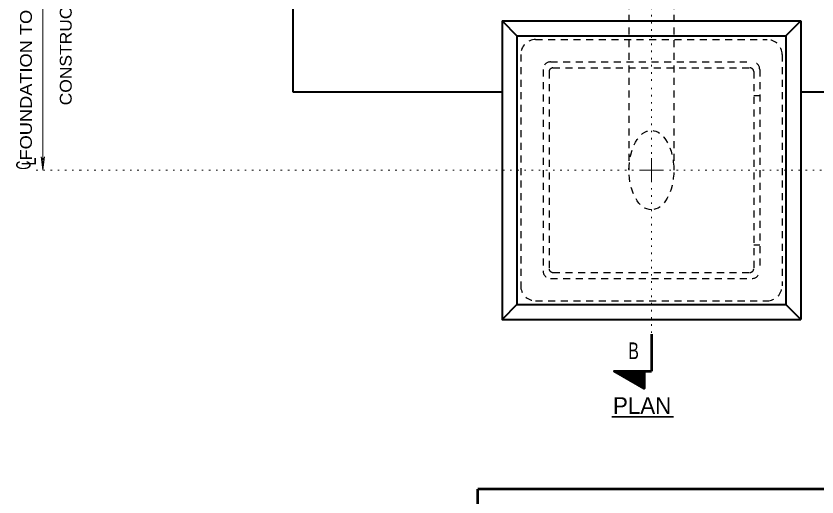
# Model space of a CAD drawing. Extents: x 312583 to 312854, y 144419 to 144597.
# Drawn here: x 312766.7 to 312818.1, y 144512 to 144542.9 of the extents above; entities that cross this region are included whole.
import ezdxf
from ezdxf.enums import TextEntityAlignment as Align

# ---------------------------------------------------------------- set-up
doc = ezdxf.new("R2010")
doc.units = 0
doc.header["$LTSCALE"] = 0.3
doc.linetypes.add('DOTTED', pattern=[1.5, 0.3, -1.2])
doc.linetypes.add('SHORT_DASHED', pattern=[2.7, 1.5, -1.2])
doc.layers.add('1', color=7, linetype='Continuous', lineweight=13)

msp = doc.modelspace()

# ---------------------------------------------------------------- linework, layer by layer
at = {"layer": '1'}
for p, q in [((312768.4232, 144532.9662), (312768.4232, 144573.9982)), ((312768.3158, 144533.8326), (312768.4232, 144533.5566)), ((312768.4232, 144532.9662), (312768.3158, 144533.8326)), ((312768.5305, 144533.8326), (312768.4232, 144533.5566)), ((312768.4232, 144532.9662), (312768.5305, 144533.8326)), ((312807.4758, 144532.9662), (312807.4758, 144533.7329)), ((312807.4758, 144532.9662), (312806.7092, 144532.9662)), ((312807.4758, 144532.9662), (312808.2425, 144532.9662)), ((312807.4758, 144532.9662), (312807.4758, 144532.1996))]:
    msp.add_line(p, q, dxfattribs=at)
at = {"layer": '1', "lineweight": 40}
for p, q in [((312784.4758, 144566.7456), (312784.4758, 144537.9956)), ((312797.8925, 144542.5496), (312817.0592, 144542.5496)), ((312797.8925, 144542.5496), (312798.8508, 144541.5912)), ((312816.1008, 144541.5912), (312817.0592, 144542.5496)), ((312817.0592, 144542.5496), (312817.0592, 144523.3829)), ((312798.8508, 144541.5912), (312798.8508, 144524.3412)), ((312798.8508, 144541.5912), (312816.1008, 144541.5912)), ((312816.1008, 144541.5912), (312816.1008, 144524.3412)), ((312784.4758, 144537.9956), (312797.8925, 144537.9956)), ((312817.0592, 144537.9956), (312830.4758, 144537.9956)), ((312798.8508, 144524.3412), (312797.8925, 144523.3829)), ((312798.8508, 144524.3412), (312816.1008, 144524.3412)), ((312816.1008, 144524.3412), (312817.0592, 144523.3829))]:
    msp.add_line(p, q, dxfattribs=at)
at = {"layer": '1', "linetype": 'DOTTED'}
for p, q in [((312807.4758, 144551.2206), (312807.4758, 144538.5706)), ((312807.4758, 144534.0166), (312807.4758, 144538.5706)), ((312807.4758, 144531.8162), (312807.4758, 144522.4476))]:
    msp.add_line(p, q, dxfattribs=at)
at = {"layer": '1', "linetype": 'SHORT_DASHED', "lineweight": 25}
for p, q in [((312806.0345, 144543.7456), (312806.0345, 144532.9662)), ((312808.9095, 144543.7456), (312808.9095, 144532.9662)), ((312800.0468, 144541.3536), (312814.8972, 144541.3536)), ((312799.0885, 144540.3952), (312799.0885, 144525.5372)), ((312815.8555, 144540.3952), (312815.8555, 144525.5372)), ((312801.0052, 144539.9122), (312813.9388, 144539.9122)), ((312800.5222, 144539.4369), (312800.5222, 144526.4956)), ((312800.9055, 144539.2912), (312800.9055, 144526.6412)), ((312801.1508, 144539.5289), (312813.8008, 144539.5289)), ((312814.0385, 144539.2912), (312814.0385, 144526.6412)), ((312814.4218, 144539.4369), (312814.4218, 144526.4956)), ((312814.0385, 144537.7579), (312814.4218, 144537.7579)), ((312814.0385, 144528.1746), (312814.4218, 144528.1746)), ((312801.1508, 144526.4036), (312813.8008, 144526.4036)), ((312801.0052, 144526.0202), (312813.9388, 144526.0202)), ((312800.0468, 144524.5789), (312814.8972, 144524.5789))]:
    msp.add_line(p, q, dxfattribs=at)
at = {"layer": '1', "lineweight": 53}
for p, q in [((312807.4758, 144522.4476), (312807.4758, 144520.0556)), ((312807.0005, 144520.0556), (312807.4758, 144520.0556)), ((312796.3473, 144432.4767), (312796.3473, 144512.4926)), ((312849, 144512.4926), (312796.3473, 144512.4926))]:
    msp.add_line(p, q, dxfattribs=at)
at = {"layer": '1', "lineweight": 35}
for p, q in [((312805.0992, 144520.0556), (312805.0992, 144520.0402)), ((312805.1298, 144520.0556), (312805.1222, 144520.0326)), ((312805.1605, 144520.0556), (312805.1375, 144520.0172)), ((312805.1835, 144520.0556), (312805.1605, 144520.0096)), ((312805.2142, 144520.0556), (312805.1835, 144519.9942)), ((312805.2372, 144520.0556), (312805.1988, 144519.9866)), ((312805.2678, 144520.0556), (312805.2218, 144519.9712)), ((312805.2985, 144520.0556), (312805.2448, 144519.9636)), ((312805.3292, 144520.0556), (312805.2602, 144519.9482)), ((312805.3522, 144520.0556), (312805.2832, 144519.9406)), ((312805.3752, 144520.0556), (312805.3062, 144519.9252)), ((312805.4058, 144520.0556), (312805.3292, 144519.9176)), ((312805.4288, 144520.0556), (312805.3445, 144519.9022)), ((312805.4595, 144520.0556), (312805.3675, 144519.8869)), ((312805.4902, 144520.0556), (312805.3905, 144519.8792)), ((312805.5208, 144520.0556), (312805.4058, 144519.8639)), ((312805.5438, 144520.0556), (312805.4288, 144519.8486)), ((312805.5745, 144520.0556), (312805.4518, 144519.8409)), ((312805.5975, 144520.0556), (312805.4672, 144519.8256)), ((312805.6282, 144520.0556), (312805.4902, 144519.8179)), ((312805.6588, 144520.0556), (312805.5132, 144519.8026)), ((312805.6818, 144520.0556), (312805.5285, 144519.7949)), ((312805.7125, 144520.0556), (312805.5592, 144519.7796)), ((312805.7355, 144520.0556), (312805.5745, 144519.7719)), ((312805.7662, 144520.0556), (312805.5975, 144519.7566)), ((312805.7968, 144520.0556), (312805.6205, 144519.7489)), ((312805.8198, 144520.0556), (312805.6358, 144519.7336)), ((312805.8505, 144520.0556), (312805.6588, 144519.7259)), ((312805.8735, 144520.0556), (312805.6818, 144519.7106)), ((312805.9042, 144520.0556), (312805.6972, 144519.6952)), ((312805.9272, 144520.0556), (312805.7202, 144519.6876)), ((312805.9578, 144520.0556), (312805.7432, 144519.6722)), ((312805.9885, 144520.0556), (312805.7585, 144519.6569)), ((312806.0192, 144520.0556), (312805.7815, 144519.6492)), ((312806.0422, 144520.0556), (312805.8045, 144519.6339)), ((312806.0652, 144520.0556), (312805.8275, 144519.6262)), ((312806.0958, 144520.0556), (312805.8428, 144519.6109)), ((312806.1265, 144520.0556), (312805.8658, 144519.6032)), ((312806.1495, 144520.0556), (312805.8888, 144519.5879)), ((312806.1802, 144520.0556), (312805.9042, 144519.5802)), ((312806.2108, 144520.0556), (312805.9272, 144519.5649)), ((312806.2338, 144520.0556), (312805.9502, 144519.5572)), ((312806.2645, 144520.0556), (312805.9655, 144519.5419)), ((312806.2952, 144520.0556), (312805.9885, 144519.5342)), ((312806.3182, 144520.0556), (312806.0115, 144519.5189)), ((312806.3488, 144520.0479), (312806.0268, 144519.5036)), ((312806.3718, 144520.0556), (312806.0575, 144519.4959)), ((312806.4025, 144520.0556), (312806.0728, 144519.4806)), ((312806.4255, 144520.0556), (312806.0958, 144519.4729)), ((312806.4562, 144520.0556), (312806.1188, 144519.4576)), ((312806.4868, 144520.0556), (312806.1342, 144519.4499)), ((312806.5175, 144520.0556), (312806.1572, 144519.4346)), ((312806.5405, 144520.0556), (312806.1802, 144519.4269)), ((312806.5635, 144520.0556), (312806.1955, 144519.4116)), ((312806.5942, 144520.0479), (312806.2185, 144519.4039)), ((312806.6248, 144520.0556), (312806.2415, 144519.3886)), ((312806.6478, 144520.0556), (312806.2568, 144519.3809)), ((312806.6785, 144520.0556), (312806.2798, 144519.3656)), ((312806.7092, 144520.0556), (312806.3028, 144519.3502)), ((312806.7322, 144520.0556), (312806.3258, 144519.3426)), ((312806.7628, 144520.0556), (312806.3412, 144519.3272)), ((312806.7935, 144520.0556), (312806.3642, 144519.3119)), ((312806.8165, 144520.0479), (312806.3872, 144519.3042)), ((312806.8472, 144520.0479), (312806.4025, 144519.2889)), ((312806.8702, 144520.0556), (312806.4255, 144519.2812)), ((312806.9008, 144520.0556), (312806.4485, 144519.2659)), ((312806.9238, 144520.0556), (312806.4638, 144519.2582)), ((312806.9545, 144520.0556), (312806.4868, 144519.2429)), ((312806.9852, 144520.0556), (312806.5098, 144519.2352)), ((312807.0005, 144520.0326), (312806.5252, 144519.2199)), ((312807.0005, 144519.9789), (312806.5558, 144519.2122)), ((312807.0005, 144519.9406), (312806.5712, 144519.1969)), ((312807.0005, 144519.8869), (312806.5942, 144519.1892)), ((312807.0005, 144519.8409), (312806.6172, 144519.1739)), ((312807.0005, 144519.7949), (312806.6325, 144519.1586)), ((312807.0005, 144519.7489), (312806.6555, 144519.1509)), ((312807.0005, 144519.6952), (312806.6785, 144519.1356)), ((312807.0005, 144519.6492), (312806.6938, 144519.1202)), ((312807.0005, 144519.6032), (312806.7168, 144519.1126)), ((312807.0005, 144519.5496), (312806.7322, 144519.0972)), ((312807.0005, 144519.5036), (312806.7552, 144519.0896)), ((312807.0005, 144519.4576), (312806.7782, 144519.0742)), ((312807.0005, 144519.4039), (312806.7935, 144519.0666)), ((312807.0005, 144519.3579), (312806.8242, 144519.0512)), ((312807.0005, 144519.3119), (312806.8395, 144519.0436)), ((312807.0005, 144519.2659), (312806.8625, 144519.0282)), ((312807.0005, 144519.2122), (312806.8855, 144519.0206)), ((312807.0005, 144519.1739), (312806.9008, 144519.0052)), ((312807.0005, 144519.1202), (312806.9238, 144518.9976)), ((312807.0005, 144519.0742), (312806.9468, 144518.9822)), ((312807.0005, 144519.0206), (312806.9622, 144518.9669)), ((312807.0005, 144518.9746), (312806.9852, 144518.9592)), ((312804.9247, 144517.1339), (312808.8875, 144517.1339))]:
    msp.add_line(p, q, dxfattribs=at)
at = {"layer": '1', "lineweight": 40}
msp.add_lwpolyline([(312797.8925, 144542.5496), (312797.8925, 144523.3829), (312817.0592, 144523.3829)], dxfattribs=at)
at = {"layer": '1', "linetype": 'DOTTED'}
for points in [[(312806.3258, 144532.9662), (312770.8698, 144532.9662), (312767.8328, 144532.9662)], [(312808.6258, 144532.9662), (312842.3325, 144532.9662), (312844.9146, 144532.9662)]]:
    msp.add_lwpolyline(points, dxfattribs=at)
at = {"layer": '1', "lineweight": 53}
msp.add_lwpolyline([(312807.0005, 144520.0556), (312807.0005, 144518.9439), (312805.0838, 144520.0556)], close=True, dxfattribs=at)
at = {"layer": '1', "linetype": 'SHORT_DASHED', "lineweight": 25}
for centre, radius, start, end in [((312800.0449, 144540.3943), 0.9583, 90, 180), ((312814.8991, 144540.3943), 0.9583, 0, 90), ((312801.0033, 144539.4359), 0.4792, 90, 180), ((312813.9408, 144539.4359), 0.4792, 0, 90), ((312801.147, 144539.2922), 0.2396, 90, 180), ((312813.797, 144539.2922), 0.2396, 0, 90), ((312801.0033, 144526.4984), 0.4792, 180, 270), ((312801.147, 144526.6422), 0.2396, 180, 270), ((312813.797, 144526.6422), 0.2396, 270, 0), ((312813.9408, 144526.4984), 0.4792, 270, 0), ((312800.0449, 144525.5401), 0.9583, 180, 270), ((312814.8991, 144525.5401), 0.9583, 270, 0)]:
    msp.add_arc(centre, radius, start, end, dxfattribs=at)
msp.add_ellipse((312807.472, 144532.9677), major_axis=(0, -2.5458), ratio=0.564653, dxfattribs=at)

# ---------------------------------------------------------------- texts
at = {"layer": '1'}
for s, height, width, p in [('  FOUNDATION TO FACE OF CURB UNLESS OTHERWISE AS SHOWN ON', 0.76, 1.15, (312767.7278, 144532.9367)), ('CONSTRUCTION PLANS OR DIRECTED BY THE ENGINEER', 0.76, 1.1, (312770.2831, 144537.1313)), ('C', 0.92, 0.65, (312767.6455, 144532.9948)), ('L', 0.92, 0.75, (312767.9905, 144533.2708))]:
    msp.add_text(s, height=height, rotation=90, dxfattribs=dict(at, width=width)).set_placement(p)
at = {"layer": '1', "width": 0.7}
msp.add_text('B', height=1.07, dxfattribs=at).set_placement((312806.3333, 144520.8365), align=Align.CENTER)
at = {"layer": '1'}
msp.add_text('PLAN', height=1.07, dxfattribs=at).set_placement((312806.878, 144517.3194), align=Align.CENTER)

doc.saveas('drawing.dxf')
